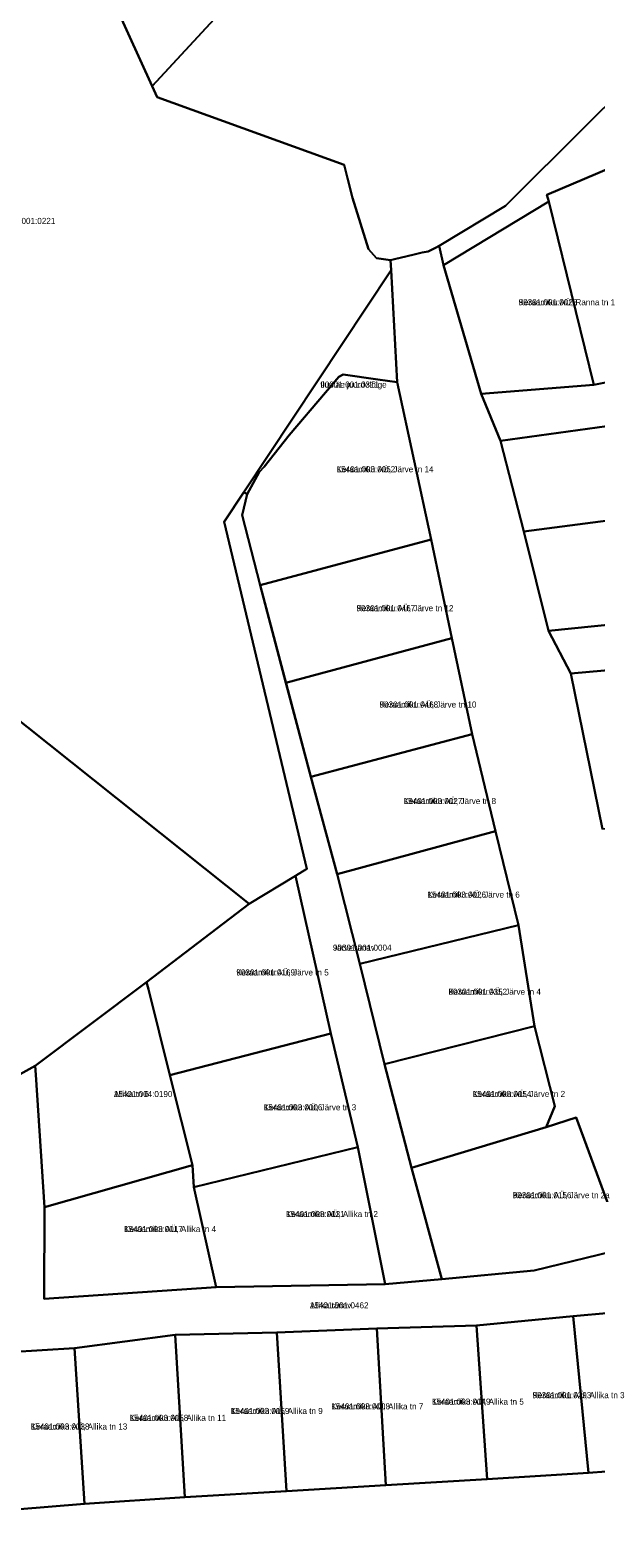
# Model space of a CAD drawing. Extents: x 634518 to 667988, y 6584667 to 6604739.
# Drawn here: x 661783.3 to 661923.2, y 6594554.3 to 6594927.4 of the extents above; entities that cross this region are included whole.
import ezdxf

# ---------------------------------------------------------------- set-up
doc = ezdxf.new("R2010")
doc.units = 0
for name, color, linetype in [('L_AADRESS', 7, 'Continuous'), ('PIIR', 7, 'Continuous'), ('TUNNUS', 7, 'Continuous')]:
    doc.layers.add(name, color=color, linetype=linetype)

msp = doc.modelspace()

# ---------------------------------------------------------------- linework, layer by layer
at = {"layer": 'PIIR'}
for points in [[(661607.8, 6595374.41), (661623.9, 6595404.86), (661684.02, 6595381.69), (661785.98, 6595144.81), (661862.64, 6594966.78), (661813.41, 6594913.52), (661732.42, 6595091.37), (661660.68, 6595254.42)], [(661973.17, 6595112.12), (662010.46, 6595162.78), (662037.55, 6595102.82), (662074.18, 6595056.38), (661903.85, 6594886.99), (661900.81, 6594883.94), (661884.44, 6594874.02), (661883.56, 6594873.54), (661881.68, 6594872.65), (661880.24, 6594872.33), (661878.61, 6594871.96), (661876.18, 6594871.39), (661873.75, 6594870.82), (661872.4, 6594870.5), (661868.9, 6594870.94), (661866.94, 6594873.21), (661862.98, 6594885.93), (661861.73, 6594890.79), (661860.89, 6594894.08), (661814.71, 6594910.83), (661813.41, 6594913.52), (661862.64, 6594966.78), (661876.64, 6594981)], [(661771.12, 6594864.12), (661677.39, 6595073.18), (661732.42, 6595091.37), (661813.41, 6594913.52), (661814.71, 6594910.83), (661860.89, 6594894.08), (661861.73, 6594890.79), (661862.98, 6594885.93), (661866.94, 6594873.21), (661868.9, 6594870.94), (661872.4, 6594870.5), (661872.56, 6594868.02), (661836.08, 6594813.04), (661831.22, 6594805.72), (661851.67, 6594719.85), (661848.86, 6594718.13), (661837.41, 6594711.19), (661722.01, 6594803.17)], [(662015.5, 6594914.68), (661990.96, 6594912.08), (661966.39, 6594908.23), (661961.99, 6594906.83), (661933.02, 6594895.92), (661911.1, 6594886.62), (661911.54, 6594885.03), (661885.54, 6594869.27), (661884.44, 6594874.02), (661900.81, 6594883.94), (661903.85, 6594886.99), (662074.18, 6595056.38), (662148.35, 6594926.69), (662170.09, 6594890.44), (662148.25, 6594888.05), (662141.41, 6594926.01), (662117.29, 6594924.33), (662090.66, 6594922.69), (662066.66, 6594920.41), (662040.97, 6594917.36)], [(661922.66, 6594839.62), (661911.54, 6594885.03), (661911.1, 6594886.62), (661933.02, 6594895.92), (661942.59, 6594860.97), (661946.77, 6594844.49)], [(661463.39, 6594691.63), (661610.97, 6594887.95), (661636.41, 6594873), (661722.01, 6594803.17), (661837.41, 6594711.19), (661812.01, 6594691.87), (661784.51, 6594671.09), (661777.22, 6594667.05), (661772.99, 6594666.58), (661735.7, 6594663.66), (661702.94, 6594660.69), (661698.32, 6594685.83), (661511.25, 6594663.94), (661498.46, 6594673.58)], [(661894.82, 6594837.36), (661885.54, 6594869.27), (661911.54, 6594885.03), (661922.66, 6594839.62)], [(661836.92, 6594812.56), (661836.08, 6594813.04), (661872.56, 6594868.02), (661874.01, 6594840.28), (661869.28, 6594840.95), (661860.71, 6594842.19), (661859.64, 6594841.57), (661856.29, 6594837.72), (661847.3, 6594827.14), (661841.18, 6594819.38), (661839.91, 6594818.01)], [(661839.91, 6594818.01), (661841.18, 6594819.38), (661847.3, 6594827.14), (661856.29, 6594837.72), (661859.64, 6594841.57), (661860.71, 6594842.19), (661869.28, 6594840.95), (661874.01, 6594840.28), (661882.42, 6594801.33), (661840.12, 6594790.06), (661835.7, 6594807.37), (661836.92, 6594812.56)], [(661905.34, 6594803.37), (661899.58, 6594825.77), (661942.68, 6594831.72), (661947.1, 6594808.82)], [(661831.22, 6594805.72), (661836.08, 6594813.04), (661836.92, 6594812.56), (661835.7, 6594807.37), (661840.12, 6594790.06), (661852.72, 6594742.61), (661859.19, 6594718.59), (661864.8, 6594696.33), (661870.89, 6594671.54), (661877.59, 6594645.87), (661885.08, 6594618.37), (661871.06, 6594617.08), (661864.27, 6594651.04), (661857.6, 6594679.11), (661848.86, 6594718.13), (661851.67, 6594719.85)], [(661911.46, 6594778.72), (661905.34, 6594803.37), (661947.1, 6594808.82), (661952.09, 6594782.9)], [(661840.12, 6594790.06), (661882.42, 6594801.33), (661887.58, 6594776.94), (661846.53, 6594765.91)], [(661852.72, 6594742.61), (661846.53, 6594765.91), (661887.58, 6594776.94), (661892.6, 6594753.2)], [(661924.83, 6594729.7), (661916.96, 6594768.23), (661941.08, 6594770.36), (661949.38, 6594731.92)], [(661859.19, 6594718.59), (661852.72, 6594742.61), (661892.6, 6594753.2), (661898.38, 6594729.17)], [(661864.8, 6594696.33), (661859.19, 6594718.59), (661898.38, 6594729.17), (661904.05, 6594705.9)], [(661812.5, 6594690.06), (661812.01, 6594691.87), (661837.41, 6594711.19), (661848.86, 6594718.13), (661857.6, 6594679.11), (661817.82, 6594668.86)], [(661904.05, 6594705.9), (661908.03, 6594680.98), (661870.89, 6594671.54), (661864.8, 6594696.33)], [(661784.65, 6594668.87), (661784.51, 6594671.09), (661812.01, 6594691.87), (661812.5, 6594690.06), (661817.82, 6594668.86), (661823.38, 6594646.52), (661786.84, 6594636.17)], [(661857.6, 6594679.11), (661864.27, 6594651.04), (661823.71, 6594641.13), (661823.38, 6594646.52), (661817.82, 6594668.86)], [(661870.89, 6594671.54), (661908.03, 6594680.98), (661913.03, 6594661.17), (661910.92, 6594655.93), (661877.59, 6594645.87)], [(661772.99, 6594666.58), (661777.22, 6594667.05), (661784.51, 6594671.09), (661784.65, 6594668.87), (661786.84, 6594636.17), (661786.72, 6594613.48), (661829.26, 6594616.38), (661871.06, 6594617.08), (661885.08, 6594618.37), (661907.96, 6594620.48), (661930.24, 6594625.96), (661935.9, 6594610.85), (661917.6, 6594609.21), (661893.7, 6594606.91), (661868.98, 6594606.11), (661844.31, 6594605.15), (661819.12, 6594604.56), (661794.19, 6594601.28), (661770.12, 6594599.82), (661769.01, 6594610.95), (661778.3, 6594611.7), (661776.11, 6594638.94)], [(661918.31, 6594658.38), (661930.24, 6594625.96), (661907.96, 6594620.48), (661885.08, 6594618.37), (661877.59, 6594645.87), (661910.92, 6594655.93)], [(661829.26, 6594616.38), (661823.71, 6594641.13), (661864.27, 6594651.04), (661871.06, 6594617.08)], [(661786.72, 6594613.48), (661786.84, 6594636.17), (661823.38, 6594646.52), (661823.71, 6594641.13), (661829.26, 6594616.38)], [(661917.6, 6594609.21), (661935.9, 6594610.85), (661951.99, 6594572.75), (661921.4, 6594570.39)], [(661868.98, 6594606.11), (661893.7, 6594606.91), (661896.29, 6594568.87), (661871.21, 6594567.37)], [(661921.4, 6594570.39), (661896.29, 6594568.87), (661893.7, 6594606.91), (661917.6, 6594609.21)], [(661794.19, 6594601.28), (661819.12, 6594604.56), (661821.55, 6594564.42), (661796.73, 6594562.72)], [(661819.12, 6594604.56), (661844.31, 6594605.15), (661846.63, 6594565.93), (661821.55, 6594564.42)], [(661846.63, 6594565.93), (661844.31, 6594605.15), (661868.98, 6594606.11), (661871.21, 6594567.37)], [(661771.61, 6594560.7), (661770.12, 6594599.82), (661794.19, 6594601.28), (661796.73, 6594562.72)], [(662053.02, 6594314.87), (662030.82, 6594306.94), (662002.72, 6594304.76), (661969.65, 6594310.52), (661952.9, 6594316.01), (661931.36, 6594332.48), (661900.65, 6594357.08), (661733.61, 6594488.34), (661689.17, 6594526.17), (661707.96, 6594555.4), (661749.99, 6594558.94), (661771.61, 6594560.7), (661796.73, 6594562.72), (661821.55, 6594564.42), (661846.63, 6594565.93), (661871.21, 6594567.37), (661896.29, 6594568.87), (661921.4, 6594570.39), (661951.99, 6594572.75), (662000.32, 6594503.25), (662048.8, 6594406.38), (662016.31, 6594387.1)]]:
    msp.add_lwpolyline(points, close=True, dxfattribs=at)
for points in [[(661930.24, 6594625.96), (661918.31, 6594658.38), (661910.92, 6594655.93), (661913.03, 6594661.17), (661908.03, 6594680.98), (661904.05, 6594705.9), (661898.38, 6594729.17), (661892.6, 6594753.2), (661887.58, 6594776.94), (661882.42, 6594801.33), (661874.01, 6594840.28), (661872.56, 6594868.02), (661872.4, 6594870.5), (661873.75, 6594870.82), (661876.18, 6594871.39), (661878.61, 6594871.96), (661880.24, 6594872.33), (661881.68, 6594872.65), (661883.56, 6594873.54), (661884.44, 6594874.02), (661885.54, 6594869.27), (661894.82, 6594837.36), (661899.58, 6594825.77), (661905.34, 6594803.37), (661911.46, 6594778.72), (661916.96, 6594768.23), (661924.83, 6594729.7)], [(661942.68, 6594831.72), (661899.58, 6594825.77), (661894.82, 6594837.36), (661922.66, 6594839.62), (661946.77, 6594844.49)], [(662190.16, 6594792.35), (662165.72, 6594789.4), (662140.59, 6594786.76), (662116.11, 6594785.1), (662091.44, 6594783.13), (662066.07, 6594780.67), (662040.43, 6594778.16), (662016.57, 6594776.09), (661990.4, 6594774.76), (661965.51, 6594772.47), (661941.08, 6594770.36), (661916.96, 6594768.23), (661911.46, 6594778.72), (661952.09, 6594782.9), (661987.24, 6594785.58), (662011.68, 6594787.45), (662037.26, 6594789.4), (662062.13, 6594791.6), (662088.56, 6594794.22), (662112.45, 6594796.74), (662122.68, 6594798.22), (662147.35, 6594799.74), (662172.57, 6594802.15), (662179.59, 6594802.52)]]:
    msp.add_lwpolyline(points, dxfattribs=at)

# ---------------------------------------------------------------- texts
at = {"layer": 'L_AADRESS'}
for s, p in [('Keraamiku AÜ, Ranna tn 1', (661904.1, 6594859.32)), ('Ilumäe juurdelõige', (661855.04, 6594838.94)), ('Keraamiku AÜ, Järve tn 14', (661859.06, 6594818)), ('Keraamiku AÜ, Järve tn 12', (661864, 6594783.62)), ('Keraamiku AÜ, Järve tn 10', (661869.68, 6594759.78)), ('Keraamiku AÜ, Järve tn 8', (661875.65, 6594735.9)), ('Keraamiku AÜ, Järve tn 6', (661881.52, 6594712.75)), ('Järve tänav', (661858.15, 6594699.62)), ('Keraamiku AÜ, Järve tn 5', (661834.26, 6594693.49)), ('Keraamiku AÜ, Järve tn 4', (661886.73, 6594688.72)), ('Allika tn 6', (661803.95, 6594663.4)), ('Keraamiku AÜ, Järve tn 2', (661892.73, 6594663.43)), ('Keraamiku AÜ, Järve tn 3', (661841.05, 6594660.12)), ('Keraamiku AÜ, Järve tn 2a', (661902.65, 6594638.38)), ('Keraamiku AÜ, Allika tn 2', (661846.55, 6594633.71)), ('Keraamiku AÜ, Allika tn 4', (661806.51, 6594630)), ('Allika tänav', (661852.45, 6594611.12)), ('Keraamiku AÜ, Allika tn 5', (661882.63, 6594587.3)), ('Keraamiku AÜ, Allika tn 3', (661907.55, 6594588.9)), ('Keraamiku AÜ, Allika tn 11', (661807.87, 6594583.28)), ('Keraamiku AÜ, Allika tn 9', (661832.88, 6594584.99)), ('Keraamiku AÜ, Allika tn 7', (661857.76, 6594586.13)), ('Keraamiku AÜ, Allika tn 13', (661783.42, 6594581.14))]:
    msp.add_text(s, height=1.5, dxfattribs=at).set_placement(p)
at = {"layer": 'TUNNUS'}
for s, p in [('15401:001:0221', (661774.98, 6594879.44)), ('90301:001:0028', (661904.1, 6594859.32)), ('90301:001:0311', (661855.04, 6594838.94)), ('15401:003:0052', (661859.06, 6594818)), ('90301:001:0467', (661864, 6594783.62)), ('90301:001:0468', (661869.68, 6594759.78)), ('15401:003:0027', (661875.65, 6594735.9)), ('15401:003:0026', (661881.52, 6594712.75)), ('90301:001:0004', (661858.15, 6594699.62)), ('90301:001:0169', (661834.26, 6594693.49)), ('90301:001:0352', (661886.73, 6594688.72)), ('15401:004:0190', (661803.95, 6594663.4)), ('15401:003:0054', (661892.73, 6594663.43)), ('15401:003:0006', (661841.05, 6594660.12)), ('90301:001:0156', (661902.65, 6594638.38)), ('15401:003:0031', (661846.55, 6594633.71)), ('15401:003:0017', (661806.51, 6594630)), ('15401:001:0462', (661852.45, 6594611.12)), ('15401:003:0049', (661882.63, 6594587.3)), ('90301:001:0293', (661907.55, 6594588.9)), ('15401:003:0058', (661807.87, 6594583.28)), ('15401:003:0059', (661832.88, 6594584.99)), ('15401:003:0008', (661857.76, 6594586.13)), ('15401:003:0038', (661783.42, 6594581.14))]:
    msp.add_text(s, height=1.5, dxfattribs=at).set_placement(p)

doc.saveas('drawing.dxf')
